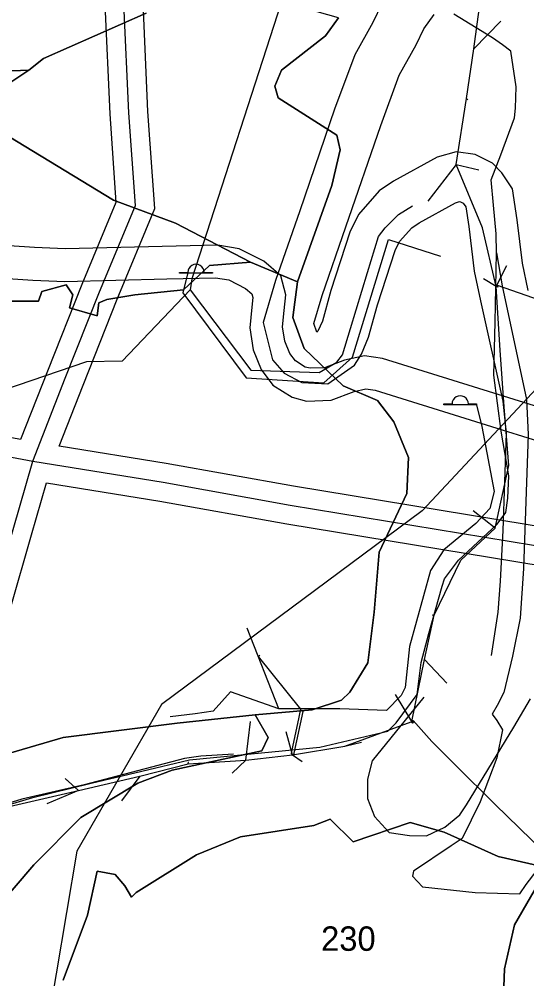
# Model space of a CAD drawing. Extents: x -694504 to -690518, y -983661 to -978958.
# Drawn here: x -692057 to -691746, y -981663 to -981074 of the extents above; entities that cross this region are included whole.
import ezdxf

# ---------------------------------------------------------------- set-up
doc = ezdxf.new("R2010")
doc.units = 0
for name, color, linetype in [('BPEJ', 7, 'Continuous'), ('kabelové a venkovní rozvody telefonu', 7, 'Continuous'), ('lokální biokoridory', 7, 'Continuous'), ('ochranné pásmo dálkového kabelu', 7, 'Continuous'), ('ochranné pásmo silnic', 7, 'Continuous'), ('ochranné pásmo vedení', 7, 'Continuous'), ('třídy přednosti v ochraně ZP', 7, 'Continuous'), ('vedení NN', 7, 'Continuous'), ('vedení VN 35kV', 7, 'Continuous'), ('vodojem', 7, 'Continuous'), ('vodovodní řad', 7, 'Continuous')]:
    doc.layers.add(name, color=color, linetype=linetype)

msp = doc.modelspace()

# ---------------------------------------------------------------- linework, layer by layer
at = {"layer": 'BPEJ'}
for points in [[(-691862.4, -981144.81), (-691898.4, -981121.81), (-691900.4, -981114.81), (-691896.4, -981104.81), (-691869.4, -981083.81), (-691861.4, -981072.81), (-691882.4, -981066.81), (-691886.4, -981058.81), (-691868.4, -981042.81), (-691859.4, -981031.81), (-691849.4, -981009.81), (-691819.4, -980959.81), (-691816.4, -980946.81), (-691809.4, -980927.81), (-691807.4, -980920.81), (-691786.4, -980900.81), (-691780.4, -980885.81), (-691768.4, -980787.81), (-691725.4, -980812.81), (-691714.4, -980819.81), (-691631.4, -980885.81), (-691615.4, -980899.81), (-691615.4, -980899.81)], [(-691979.4, -981069.81), (-692042.4, -981097.81), (-692051.4, -981104.81), (-692098.4, -981106.81), (-692098.4, -981115.81), (-692090.4, -981122.81), (-692079.4, -981119.81), (-692101.4, -981139.81), (-692175.4, -981146.81), (-692210.4, -981144.81), (-692273.4, -981121.81), (-692279.4, -981119.81), (-692349.4, -981069.81)], [(-691861.4, -981072.81), (-691869.4, -981083.81), (-691896.4, -981104.81), (-691900.4, -981114.81), (-691898.4, -981121.81), (-691862.4, -981144.81), (-691860.4, -981153.81), (-691865.4, -981175.81), (-691886.4, -981234.81), (-691915.4, -981222.81), (-691961.4, -981198.81), (-691999.4, -981184.81), (-692068.4, -981142.81), (-692085.4, -981138.81), (-692101.4, -981139.81), (-692079.4, -981119.81), (-692069.4, -981116.81), (-692051.4, -981104.81), (-692042.4, -981097.81), (-691979.4, -981069.81)], [(-692068.4, -981142.81), (-691999.4, -981184.81), (-691961.4, -981198.81), (-691915.4, -981222.81), (-691940.4, -981224.81), (-691956.4, -981239.81), (-691986.4, -981242.81), (-692003.4, -981245.81), (-692008.4, -981247.81), (-692009.4, -981255.81), (-692026.4, -981250.81), (-692024.4, -981242.81), (-692028.4, -981236.81), (-692043.4, -981240.81), (-692045.4, -981246.81), (-692071.4, -981246.81)], [(-692071.4, -981619.81), (-692048.4, -981592.81), (-692019.4, -981563.81), (-691984.4, -981542.81), (-691963.4, -981534.81), (-691908.4, -981522.81), (-691904.4, -981514.81), (-691912.4, -981500.81), (-691877.4, -981497.81), (-691859.4, -981491.81), (-691854.4, -981486.81), (-691843.4, -981468.81), (-691839.4, -981437.81), (-691836.4, -981400.81), (-691819.4, -981364.81), (-691818.4, -981342.81), (-691827.4, -981320.81), (-691837.4, -981307.81), (-691858.4, -981298.81), (-691882.4, -981275.81), (-691889.4, -981256.81), (-691886.4, -981234.81), (-691865.4, -981175.81), (-691860.4, -981153.81), (-691862.4, -981144.81)], [(-692071.4, -981246.81), (-692045.4, -981246.81), (-692043.4, -981240.81), (-692028.4, -981236.81), (-692024.4, -981242.81), (-692026.4, -981250.81), (-692009.4, -981255.81), (-692008.4, -981247.81), (-692003.4, -981245.81), (-691986.4, -981242.81), (-691956.4, -981239.81), (-691940.4, -981224.81), (-691915.4, -981222.81), (-691915.4, -981222.81), (-691886.4, -981234.81), (-691889.4, -981256.81), (-691882.4, -981275.81), (-691858.4, -981298.81), (-691837.4, -981307.81), (-691827.4, -981320.81), (-691818.4, -981342.81), (-691819.4, -981364.81), (-691836.4, -981400.81), (-691839.4, -981437.81), (-691843.4, -981468.81), (-691854.4, -981486.81), (-691859.4, -981491.81), (-691877.4, -981497.81), (-691912.4, -981500.81), (-691960.4, -981505.81), (-692030.4, -981514.81), (-692109.4, -981537.81)], [(-692109.4, -981537.81), (-692030.4, -981514.81), (-691960.4, -981505.81), (-691912.4, -981500.81), (-691904.4, -981514.81), (-691908.4, -981522.81), (-691963.4, -981534.81), (-691984.4, -981542.81), (-692019.4, -981563.81), (-692048.4, -981592.81), (-692071.4, -981619.81)], [(-691737.4, -981593.81), (-691763.4, -981587.81), (-691796.4, -981572.81), (-691817.4, -981566.81), (-691852.4, -981578.81), (-691866.4, -981564.81), (-691876.4, -981568.81), (-691921.4, -981575.81), (-691948.4, -981586.81), (-691985.4, -981609.81), (-691988.4, -981612.81), (-691992.4, -981605.81), (-691998.4, -981598.81), (-692009.4, -981596.81), (-692015.4, -981623.81), (-692030.4, -981663.81)], [(-692030.4, -981663.81), (-692015.4, -981623.81), (-692009.4, -981596.81), (-691998.4, -981598.81), (-691992.4, -981605.81), (-691988.4, -981612.81), (-691985.4, -981609.81), (-691948.4, -981586.81), (-691921.4, -981575.81), (-691876.4, -981568.81), (-691866.4, -981564.81), (-691852.4, -981578.81), (-691817.4, -981566.81), (-691796.4, -981572.81), (-691763.4, -981587.81), (-691737.4, -981593.81), (-691731.4, -981591.81), (-691731.4, -981591.81), (-691753.4, -981629.81), (-691759.4, -981656.81), (-691761.4, -981706.81)], [(-691761.4, -981706.81), (-691759.4, -981656.81), (-691753.4, -981629.81), (-691731.4, -981591.81)]]:
    msp.add_lwpolyline(points, dxfattribs=at)
msp.add_lwpolyline([(-692079.4, -981119.81), (-692090.4, -981122.81), (-692098.4, -981115.81), (-692098.4, -981106.81), (-692051.4, -981104.81), (-692069.4, -981116.81), (-692079.4, -981119.81)], close=True, dxfattribs=at)
at = {"layer": 'kabelové a venkovní rozvody telefonu'}
for points in [[(-692077.19, -981559.95), (-692048.89, -981551.49), (-692013.06, -981542.84), (-691981.95, -981535.35), (-691952.8, -981528.49), (-691872.85, -981520.58), (-691831.1, -981510.87), (-691826, -981505.77), (-691813.01, -981488.34), (-691810.66, -981468.61), (-691805.98, -981450.78), (-691797.67, -981421.81), (-691796.34, -981417.18), (-691787.74, -981405.75), (-691764.03, -981383.78), (-691758.65, -981376.6), (-691757.46, -981367.66), (-691756.87, -981354.11), (-691761.56, -981326.53), (-691765.98, -981292.19), (-691765.1, -981259.7), (-691764.45, -981217.1), (-691764.52, -981205.33), (-691766.24, -981187.7), (-691767.56, -981172.21), (-691761.63, -981156.92), (-691753.39, -981134.1), (-691752.8, -981128.17), (-691752.21, -981115.21), (-691755.47, -981093.28), (-691760.62, -981089.4), (-691766.8, -981084.99), (-691790.45, -981070.56)], [(-691764.45, -981217.1), (-691760.94, -981237.3), (-691746, -981307.06), (-691744.84, -981328.69), (-691747.77, -981410.96), (-691749.82, -981441.36), (-691754.52, -981464.78), (-691759.94, -981487.01), (-691763.9, -981495.15), (-691767.01, -981500.37), (-691764.26, -981504.22), (-691760.63, -981509.97), (-691764.19, -981527.2), (-691774.45, -981554.12), (-691785.35, -981576.83), (-691792.2, -981581.29), (-691815.21, -981596.88), (-691815.98, -981599.95), (-691809.85, -981606.35), (-691777.55, -981609.85), (-691750.02, -981610.72), (-691746.07, -981605.07), (-691734.68, -981590.08)]]:
    msp.add_lwpolyline(points, dxfattribs=at)
at = {"layer": 'lokální biokoridory'}
for points in [[(-691657.68, -981337.11), (-691834.25, -981281.95), (-691845.37, -981280.27), (-691857.55, -981283.03), (-691869.85, -981287.65), (-691878.81, -981287.99), (-691881.73, -981287.21), (-691887.81, -981283.45), (-691891.25, -981278.8), (-691894.32, -981271.27), (-691895.63, -981262.59), (-691894.66, -981252.43), (-691893.71, -981242.94), (-691896.75, -981231.21), (-691907.25, -981222.21), (-691922.3, -981214.53), (-691935.33, -981212.31), (-692029.02, -981214.64), (-692047.9, -981213.89), (-692131.91, -981208.27)], [(-692134.55, -981228.14), (-692048.96, -981233.86), (-692029.18, -981234.65), (-691966.73, -981233.1), (-691936.78, -981232.35), (-691928.67, -981233.73), (-691918.46, -981238.94), (-691914.53, -981242.31), (-691913.96, -981244.5), (-691914.56, -981250.48), (-691915.78, -981263.13), (-691913.74, -981276.62), (-691908.82, -981288.67), (-691901.61, -981298.43), (-691889.73, -981305.78), (-691881.05, -981308.09), (-691865.86, -981307.51), (-691851.79, -981302.23), (-691844.64, -981300.61), (-691838.75, -981301.5), (-691667.11, -981355.12)]]:
    msp.add_lwpolyline(points, dxfattribs=at)
at = {"layer": 'ochranné pásmo dálkového kabelu'}
msp.add_lwpolyline([(-691386.18, -980026.89), (-691386.18, -980026.89), (-691386.18, -980026.89), (-691386.18, -980026.89), (-691374.89, -980105.48), (-691346.89, -980518.48), (-691469.89, -980660.48), (-691539.89, -980845.48), (-691610.89, -981162.48), (-691809.89, -981375.48), (-691969.89, -981494.48), (-692021.89, -981584.48), (-692040.89, -981697.48), (-692016.89, -981835.48), (-692032.89, -981838.48)], dxfattribs=at)
at = {"layer": 'ochranné pásmo silnic'}
for points in [[(-691834.8, -981064.21), (-691840.31, -981075.51), (-691851.38, -981095.38), (-691863.7, -981128.85), (-691885.14, -981191.36), (-691899.94, -981234.08), (-691907.49, -981259.79), (-691901.93, -981282.78), (-691894.71, -981290.94), (-691883.84, -981296.76), (-691867.85, -981297.58), (-691851.56, -981286.13), (-691847.3, -981279.22), (-691842.85, -981268.88), (-691837.39, -981248.9), (-691826.48, -981215.67), (-691823.8, -981210.15), (-691816.33, -981201.62), (-691811.92, -981198.6), (-691789.52, -981186.28), (-691787.16, -981185.64), (-691786.39, -981185.75), (-691784.83, -981186.52), (-691783.23, -981188.76), (-691781.43, -981200.85), (-691778.03, -981228.33), (-691774.28, -981246.58), (-691760.41, -981308.16), (-691758.53, -981327.9), (-691760.55, -981387.52), (-691762.08, -981418.63), (-691763.57, -981437.72), (-691767.62, -981464.37)], [(-691744.95, -981240.26), (-691748.41, -981223.45), (-691751.71, -981196.8), (-691754.55, -981177.7), (-691761.01, -981168.01), (-691766.87, -981161.91), (-691777.42, -981156.74), (-691789.02, -981155.05), (-691800.85, -981158.28), (-691827.67, -981173.02), (-691836.41, -981179.02), (-691849.04, -981193.43), (-691854.35, -981204.4), (-691866.13, -981240.26), (-691871.23, -981258.94), (-691873.92, -981265.18), (-691874.66, -981265.7), (-691876.44, -981260.54), (-691871.36, -981243.22), (-691856.78, -981201.14), (-691835.43, -981138.9), (-691824.04, -981107.93), (-691813.71, -981089.4), (-691808.91, -981079.56), (-691802.68, -981070.76)], [(-691808.99, -981489.89), (-691840.76, -981529.1), (-691843.56, -981540.3), (-691843.56, -981552.25), (-691839.17, -981563.21), (-691830.27, -981573.1), (-691817.67, -981574.9), (-691807.33, -981575.13), (-691796.08, -981569.85), (-691786.79, -981562.1), (-691782.69, -981556.05), (-691753.67, -981508.43), (-691743.55, -981490.93)]]:
    msp.add_lwpolyline(points, dxfattribs=at)
at = {"layer": 'ochranné pásmo vedení'}
for points in [[(-691792.72, -980931.21), (-691822.1, -980903.17), (-691864.46, -980860.54), (-691913.85, -980906.25), (-691959.7, -980946.13), (-692009.06, -980988.9), (-692004.73, -981064.6), (-692001.73, -981131.67), (-691997.92, -981186.06), (-692018.89, -981236.58), (-692039.93, -981289.69), (-692056.39, -981331.65), (-692131.85, -981317.45), (-692234.86, -981298.45), (-692432.9, -981261.44), (-692500.89, -981249.44), (-692585.86, -981233.45), (-692655.55, -981220.75), (-692739.96, -981204.97), (-692834.02, -981187.35)], [(-691558.97, -981380.3), (-691573.82, -981399.76), (-691582.36, -981410.87), (-691889.01, -981360.42), (-691967.02, -981346.42), (-692032.75, -981335.74), (-692018.07, -981298.31), (-691997.11, -981245.42), (-691974.08, -981189.94), (-691978.27, -981130.33), (-691981.27, -981063.4), (-691984.94, -980999.1), (-691944.3, -980963.87), (-691898.15, -980923.75), (-691865.14, -980893.19), (-691838.56, -980919.95), (-691807.63, -980949.47)], [(-692098.78, -981564.62), (-692085.68, -981520.16), (-692075.66, -981482.06), (-692062.69, -981435.2), (-692049.71, -981390.24), (-692040.57, -981358.27), (-691970.98, -981369.58), (-691892.99, -981383.58), (-691578.35, -981435.35), (-691505.97, -981436.12), (-691403.79, -981436.1), (-691320.85, -981435.75), (-691226.93, -981433.75), (-691115.11, -981434.75), (-691018, -981435.75), (-690919.94, -981434.75), (-690865, -981434.75), (-690798.01, -981434.75), (-690720.4, -981434.84), (-690660.99, -981434.75), (-690632.73, -981444.66)]]:
    msp.add_lwpolyline(points, dxfattribs=at)
at = {"layer": 'vedení NN'}
for points in [[(-691778.36, -981091.82), (-691772.72, -981050.74)], [(-691778.36, -981091.82), (-691761.78, -981074.73)], [(-691782.87, -981122.23), (-691778.36, -981091.82)], [(-691789.11, -981162.81), (-691782.87, -981122.23)], [(-691782.87, -981122.23), (-691781.94, -981123.08)], [(-691789.11, -981162.81), (-691806.53, -981185.43)], [(-691764.65, -981237.79), (-691772.95, -981201.71), (-691789.11, -981162.81)], [(-691789.11, -981162.81), (-691775.15, -981166.17)], [(-691764.65, -981237.79), (-691758.01, -981224.89)], [(-691764.65, -981237.79), (-691772.43, -981233.08)], [(-691765.12, -981386.07), (-691756.83, -981347.72), (-691759.62, -981311.74), (-691762.1, -981276.78), (-691764.65, -981237.79)], [(-691763.57, -981237.94), (-691763.64, -981238.13), (-691764.65, -981237.79)], [(-691763.57, -981237.94), (-691763.49, -981237.76), (-691764.2, -981237.51), (-691763.95, -981236.93), (-691728.83, -981249.2), (-691698.83, -981258.33), (-691661.28, -981270.39), (-691629.29, -981280.71)], [(-691765.12, -981386.07), (-691778.77, -981375.45)], [(-691802.7, -981439.68), (-691786.18, -981405.74), (-691765.12, -981386.07)], [(-691808.64, -981466.87), (-691802.7, -981439.68)], [(-691803.93, -981439.38), (-691802.7, -981439.68)], [(-691889.56, -981525.4), (-691890.22, -981524.58), (-691889.94, -981523.29), (-691888.5, -981516.59), (-691886.29, -981506.16), (-691884.42, -981497.34), (-691910.49, -981464.97), (-691909.52, -981464.14)], [(-691816.38, -981504.78), (-691808.64, -981466.87)], [(-691808.64, -981466.87), (-691794.91, -981481.27)], [(-691816.38, -981504.78), (-691826.3, -981488.4)], [(-691889.56, -981525.4), (-691888.66, -981524.85), (-691888.51, -981524.37), (-691883.11, -981498.77), (-691883.9, -981498.63)], [(-691918.25, -981528.72), (-691915.34, -981504.81)], [(-691857.48, -981520.08), (-691816.68, -981505.05)], [(-691815.54, -981505.69), (-691815.82, -981505.98), (-691816.68, -981505.05)], [(-691815.54, -981505.69), (-691816.38, -981504.78)], [(-691815.54, -981505.69), (-691815.26, -981505.41), (-691815.87, -981504.74), (-691815.48, -981504.34), (-691804.05, -981517.19), (-691789.57, -981531.73), (-691765.19, -981555.79), (-691735.59, -981584.81)], [(-691889.56, -981525.4), (-691893.54, -981511.24)], [(-691857.48, -981520.08), (-691847.12, -981517.66)], [(-691889.56, -981525.4), (-691857.48, -981520.08)], [(-691953.5, -981530.84), (-691918.25, -981528.72)], [(-691953.5, -981530.84), (-691953.43, -981529.55)], [(-691918.25, -981528.72), (-691926.61, -981536.53)], [(-691918.25, -981528.72), (-691889.56, -981525.4)], [(-691889.56, -981525.4), (-691883.73, -981529.53)], [(-691983.31, -981538.4), (-691953.5, -981530.84)], [(-692020.86, -981547.32), (-692028.98, -981539.87), (-692028.14, -981540.82)], [(-692020.86, -981547.32), (-691983.31, -981538.4)], [(-691983.31, -981538.4), (-691994.54, -981553.62)], [(-692092.46, -981575.4), (-692063.34, -981556.99), (-692020.86, -981547.32)], [(-692020.86, -981547.32), (-692040.24, -981555.35)]]:
    msp.add_lwpolyline(points, dxfattribs=at)
at = {"layer": 'vedení VN 35kV'}
for points in [[(-692109.51, -981559.46), (-692097, -981517), (-692087, -981479), (-692074, -981432), (-692061, -981387), (-692049, -981345), (-692029, -981294), (-692008, -981241), (-691986, -981188), (-691990, -981131), (-691993, -981064), (-691997, -980994), (-691952, -980955), (-691906, -980915), (-691864.8, -980876.87), (-691830.33, -980911.56), (-691803.29, -980937.37)], [(-692836.19, -981198.9), (-692742.12, -981216.52), (-692657.68, -981232.3), (-692588, -981245), (-692503, -981261), (-692435, -981273), (-692237, -981310), (-692134, -981329), (-692049, -981345), (-691969, -981358), (-691891, -981372), (-691577.33, -981423.61), (-691505.91, -981424.37), (-691403.82, -981424.35), (-691321, -981424), (-691227, -981422), (-691115, -981423), (-691018, -981424), (-690920, -981423), (-690865, -981423), (-690798, -981423), (-690720.41, -981423.09), (-690659, -981423), (-690630.93, -981432.84)]]:
    msp.add_lwpolyline(points, dxfattribs=at)
at = {"layer": 'vodojem'}
for p, q in [((-691958.84, -981229.1), (-691953.84, -981229.1)), ((-691958.84, -981229.63), (-691958.84, -981229.1)), ((-691958.84, -981229.63), (-691958.84, -981229.1)), ((-691958.84, -981229.1), (-691953.84, -981229.1)), ((-691943.77, -981229.09), (-691938.73, -981229.09)), ((-691943.77, -981229.09), (-691938.73, -981229.09)), ((-691938.73, -981229.09), (-691938.73, -981229.63)), ((-691938.73, -981229.09), (-691938.73, -981229.63)), ((-691938.73, -981229.63), (-691958.84, -981229.63)), ((-691938.73, -981229.63), (-691958.84, -981229.63)), ((-691796.67, -981309.82), (-691791.66, -981309.82)), ((-691796.67, -981310.35), (-691796.67, -981309.82)), ((-691796.67, -981310.35), (-691796.67, -981309.82)), ((-691796.67, -981309.82), (-691791.66, -981309.82)), ((-691776.56, -981310.35), (-691796.67, -981310.35)), ((-691776.56, -981310.35), (-691796.67, -981310.35)), ((-691781.59, -981309.81), (-691776.56, -981309.81)), ((-691781.59, -981309.81), (-691776.56, -981309.81)), ((-691776.56, -981309.81), (-691776.56, -981310.35)), ((-691776.56, -981309.81), (-691776.56, -981310.35))]:
    msp.add_line(p, q, dxfattribs=at)
for centre in [(-691948.8, -981229.08), (-691948.8, -981229.08), (-691786.63, -981309.81), (-691786.63, -981309.81)]:
    msp.add_ellipse(centre, major_axis=(-5.03, 0), ratio=0.990986, start_param=3.141359, end_param=6.28742, dxfattribs=at)
at = {"layer": 'vodovodní řad'}
for points in [[(-691894.19, -981056.37), (-691951.24, -981233.09), (-691952.28, -981239.87), (-691915.07, -981289.04), (-691873.13, -981290.54), (-691862.27, -981284.17), (-691858.89, -981279.67), (-691854.03, -981263.56), (-691843.54, -981229.09), (-691836.8, -981206.98), (-691832.68, -981201.73), (-691824.44, -981193.49), (-691815.82, -981188.24)], [(-691953.84, -981229.1), (-691956.91, -981241.53), (-691917.93, -981293.92), (-691870.23, -981296.83), (-691852.78, -981281.11), (-691830.67, -981208.93), (-691798.66, -981219.12)], [(-691952.28, -981239.87), (-691994.16, -981283.53), (-692016.03, -981284.05), (-692075.58, -981304.29), (-692142.96, -981360.36), (-692143.71, -981380.97), (-692213.37, -981379.85), (-692228.6, -981388.76), (-692264.18, -981392.95), (-692318.32, -981437.42), (-692356, -981468.38)], [(-691776.56, -981310.35), (-691773.28, -981323.81), (-691765.71, -981363.56), (-691768.42, -981374.11), (-691777.07, -981383.3), (-691796.74, -981399.4), (-691804.85, -981412.11), (-691817.77, -981458.78), (-691820.47, -981483.93), (-691822.89, -981489.01), (-691831.81, -981498.2), (-691860.46, -981497.12), (-691897.94, -981497.12), (-691917.47, -981447.62)], [(-691897.94, -981497.12), (-691927.67, -981486.57), (-691938.21, -981498.47), (-691949.29, -981500.09), (-691964.7, -981501.99)], [(-691925.74, -981524.9), (-691945.82, -981526.14), (-691955.93, -981527.64), (-692017.33, -981543.71), (-692055.72, -981552.66), (-692075.66, -981558.63), (-692084.97, -981565.71), (-692094.1, -981573.73), (-692107.3, -981592.51), (-692116.79, -981607.21), (-692135.79, -981635.34), (-692140.82, -981641.12), (-692173.93, -981667.53)]]:
    msp.add_lwpolyline(points, dxfattribs=at)

# ---------------------------------------------------------------- texts
at = {"layer": 'třídy přednosti v ochraně ZP'}
msp.add_text('230', height=15, dxfattribs=at).set_placement((-691872, -981645.72))

doc.saveas('drawing.dxf')
